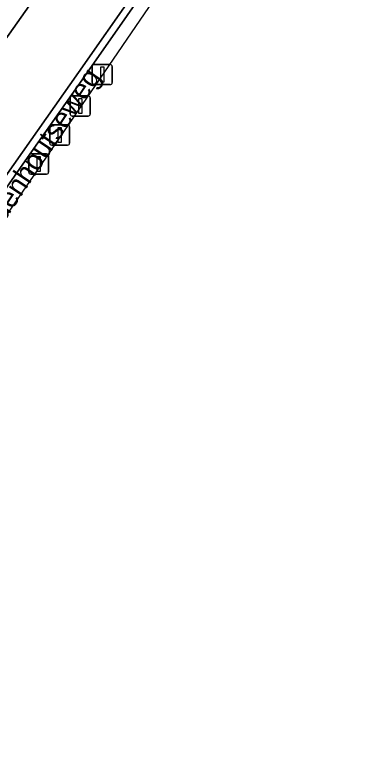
# Model space of a CAD drawing. Extents: x 157132 to 159279, y 384991 to 386650.
# Drawn here: x 159162.05 to 159179.3, y 385090.09 to 385127.03 of the extents above; entities that cross this region are included whole.
import ezdxf

# ---------------------------------------------------------------- set-up
doc = ezdxf.new("R2010")
doc.units = 0
for name, color, linetype in [('IMGEO_Afsluitpaal', 7, 'Continuous'), ('IMGEO_Berm_groen', 7, 'Continuous'), ('IMGEO_Openbare_ruimte_label', 7, 'Continuous'), ('IMGEO_Rijbaan_lokaal_gesloten', 7, 'Continuous'), ('IMGEO_Rijbaan_lokaal_halfverhard', 7, 'Continuous'), ('IMGEO_Voetpad_open', 7, 'Continuous')]:
    doc.layers.add(name, color=color, linetype=linetype)

msp = doc.modelspace()

# ---------------------------------------------------------------- linework, layer by layer
at = {"layer": 'IMGEO_Afsluitpaal'}
for p, q in [((159165.894, 385123.667), (159165.894, 385124.467)), ((159165.894, 385124.467), (159165.894, 385123.667)), ((159165.994, 385124.567), (159166.784, 385124.567)), ((159166.784, 385124.567), (159165.994, 385124.567)), ((159166.884, 385124.467), (159166.884, 385123.667)), ((159166.884, 385123.667), (159166.884, 385124.467)), ((159166.784, 385123.567), (159165.994, 385123.567)), ((159165.994, 385123.567), (159166.784, 385123.567)), ((159164.798, 385122.106), (159164.798, 385122.906)), ((159164.798, 385122.906), (159164.798, 385122.106)), ((159164.898, 385123.006), (159165.688, 385123.006)), ((159165.688, 385123.006), (159164.898, 385123.006)), ((159165.788, 385122.906), (159165.788, 385122.106)), ((159165.788, 385122.106), (159165.788, 385122.906)), ((159165.688, 385122.006), (159164.898, 385122.006)), ((159164.898, 385122.006), (159165.688, 385122.006)), ((159163.779, 385120.669), (159163.779, 385121.469)), ((159163.779, 385121.469), (159163.779, 385120.669)), ((159163.879, 385121.569), (159164.669, 385121.569)), ((159164.669, 385121.569), (159163.879, 385121.569)), ((159164.769, 385121.469), (159164.769, 385120.669)), ((159164.769, 385120.669), (159164.769, 385121.469)), ((159164.669, 385120.569), (159163.879, 385120.569)), ((159163.879, 385120.569), (159164.669, 385120.569)), ((159162.733, 385119.227), (159162.733, 385120.027)), ((159162.733, 385120.027), (159162.733, 385119.227)), ((159162.833, 385120.127), (159163.623, 385120.127)), ((159163.623, 385120.127), (159162.833, 385120.127)), ((159163.723, 385120.027), (159163.723, 385119.227)), ((159163.723, 385119.227), (159163.723, 385120.027)), ((159163.623, 385119.127), (159162.833, 385119.127)), ((159162.833, 385119.127), (159163.623, 385119.127))]:
    msp.add_line(p, q, dxfattribs=at)
for points in [[(159166.314, 385124.442), (159166.464, 385124.442), (159166.464, 385123.692), (159166.314, 385123.692), (159166.314, 385124.442)], [(159165.218, 385122.881), (159165.368, 385122.881), (159165.368, 385122.131), (159165.218, 385122.131), (159165.218, 385122.881)], [(159164.199, 385121.444), (159164.349, 385121.444), (159164.349, 385120.694), (159164.199, 385120.694), (159164.199, 385121.444)], [(159163.153, 385120.002), (159163.303, 385120.002), (159163.303, 385119.252), (159163.153, 385119.252), (159163.153, 385120.002)]]:
    msp.add_lwpolyline(points, dxfattribs=at)
for centre, start, end in [((159165.994, 385124.467), 90, 180), ((159165.994, 385124.467), 90, 180), ((159166.784, 385124.467), 0, 90), ((159166.784, 385124.467), 360, 90), ((159165.994, 385123.667), 180, 270), ((159165.994, 385123.667), 180, 270), ((159166.784, 385123.667), 270, 0), ((159166.784, 385123.667), 270, 0), ((159164.898, 385122.906), 90, 180), ((159164.898, 385122.906), 90, 180), ((159165.688, 385122.906), 0, 90), ((159165.688, 385122.906), 360, 90), ((159164.898, 385122.106), 180, 270), ((159164.898, 385122.106), 180, 270), ((159165.688, 385122.106), 270, 0), ((159165.688, 385122.106), 270, 0), ((159163.879, 385121.469), 90, 180), ((159163.879, 385121.469), 90, 180), ((159164.669, 385121.469), 0, 90), ((159164.669, 385121.469), 360, 90), ((159163.879, 385120.669), 180, 270), ((159163.879, 385120.669), 180, 270), ((159164.669, 385120.669), 270, 0), ((159164.669, 385120.669), 270, 0), ((159162.833, 385120.027), 90, 180), ((159162.833, 385120.027), 90, 180), ((159163.623, 385120.027), 0, 90), ((159163.623, 385120.027), 360, 90), ((159162.833, 385119.227), 180, 270), ((159162.833, 385119.227), 180, 270), ((159163.623, 385119.227), 270, 0), ((159163.623, 385119.227), 270, 0)]:
    msp.add_arc(centre, 0.1, start, end, dxfattribs=at)
at = {"layer": 'IMGEO_Berm_groen'}
msp.add_lwpolyline([(159163.18, 385119.339), (159183.989, 385149.748), (159180.021, 385144.473), (159173.992, 385136.096), (159165.503, 385123.964), (159162.556, 385119.784), (159163.18, 385119.339)], dxfattribs=at)
at = {"layer": 'IMGEO_Rijbaan_lokaal_gesloten'}
for points in [[(159107.116, 385039.583), (159113.235, 385048.651), (159133.732, 385079.03), (159149.547, 385101.952), (159165.213, 385124.168), (159173.703, 385136.301), (159179.735, 385144.683), (159187.963, 385155.555), (159214.022, 385193.636)], [(159193.211, 385168.845), (159187.56, 385161.643), (159181.331, 385153.165), (159172.644, 385141.459), (159166.702, 385133.073), (159158.593, 385121.626), (159152.041, 385112.291), (159143.441, 385100.038), (159135.503, 385088.629), (159130.039, 385080.599), (159124.39, 385072.298), (159120.076, 385065.821), (159112.721, 385054.945), (159108.114, 385048.109)]]:
    msp.add_lwpolyline(points, dxfattribs=at)
at = {"layer": 'IMGEO_Rijbaan_lokaal_halfverhard'}
for points in [[(159108.114, 385048.109), (159112.721, 385054.945), (159120.076, 385065.821), (159124.39, 385072.298), (159130.039, 385080.599), (159135.503, 385088.629), (159143.441, 385100.038), (159152.041, 385112.291), (159158.593, 385121.626), (159166.702, 385133.073), (159172.644, 385141.459), (159181.331, 385153.165), (159187.56, 385161.643), (159193.211, 385168.845)], [(159109.102, 385041.893), (159110.79, 385044.395), (159113.528, 385048.453), (159126.657, 385067.912), (159128.344, 385070.412), (159134.024, 385078.831), (159143.607, 385092.719), (159145.304, 385095.179), (159149.838, 385101.749), (159160.83, 385117.337), (159162.556, 385119.784), (159165.503, 385123.964), (159173.992, 385136.096), (159180.021, 385144.473), (159183.989, 385149.748), (159187.963, 385155.555), (159179.735, 385144.683), (159173.703, 385136.301), (159165.213, 385124.168), (159149.547, 385101.952), (159133.732, 385079.03), (159113.235, 385048.651), (159107.116, 385039.583)]]:
    msp.add_lwpolyline(points, dxfattribs=at)
at = {"layer": 'IMGEO_Voetpad_open'}
msp.add_lwpolyline([(159161.48, 385116.856), (159163.18, 385119.339), (159162.556, 385119.784), (159160.83, 385117.337), (159161.48, 385116.856)], dxfattribs=at)

# ---------------------------------------------------------------- texts
at = {"layer": 'IMGEO_Openbare_ruimte_label'}
msp.add_text('Bezuidenhoutseweg', height=1, rotation=56.2146, dxfattribs=at).set_placement((159159.65, 385113.948))

doc.saveas('drawing.dxf')
